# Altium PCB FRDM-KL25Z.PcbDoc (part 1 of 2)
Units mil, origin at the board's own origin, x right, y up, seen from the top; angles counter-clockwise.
Board outline 3200 x 2100 mil, 2 copper layers (Top Layer, Bottom Layer), stack 42.17 mil thick; 0 components, 164 nets, 466 pads, 402 vias.
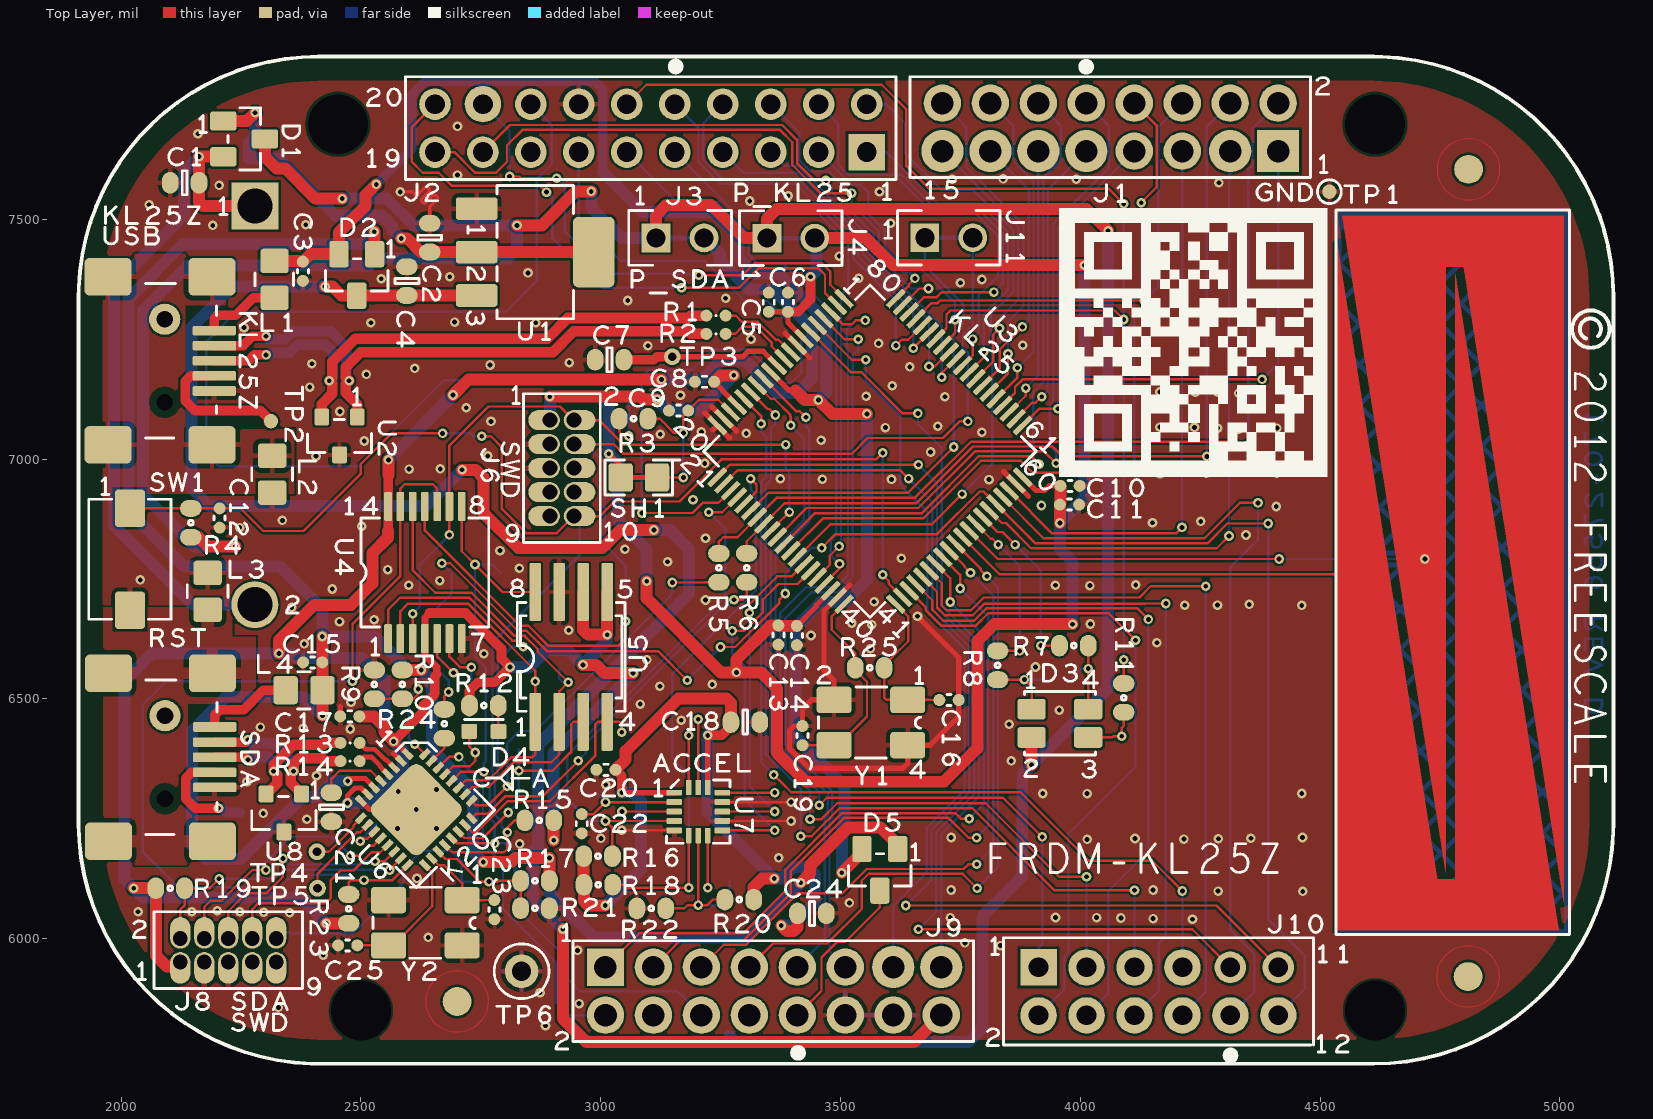
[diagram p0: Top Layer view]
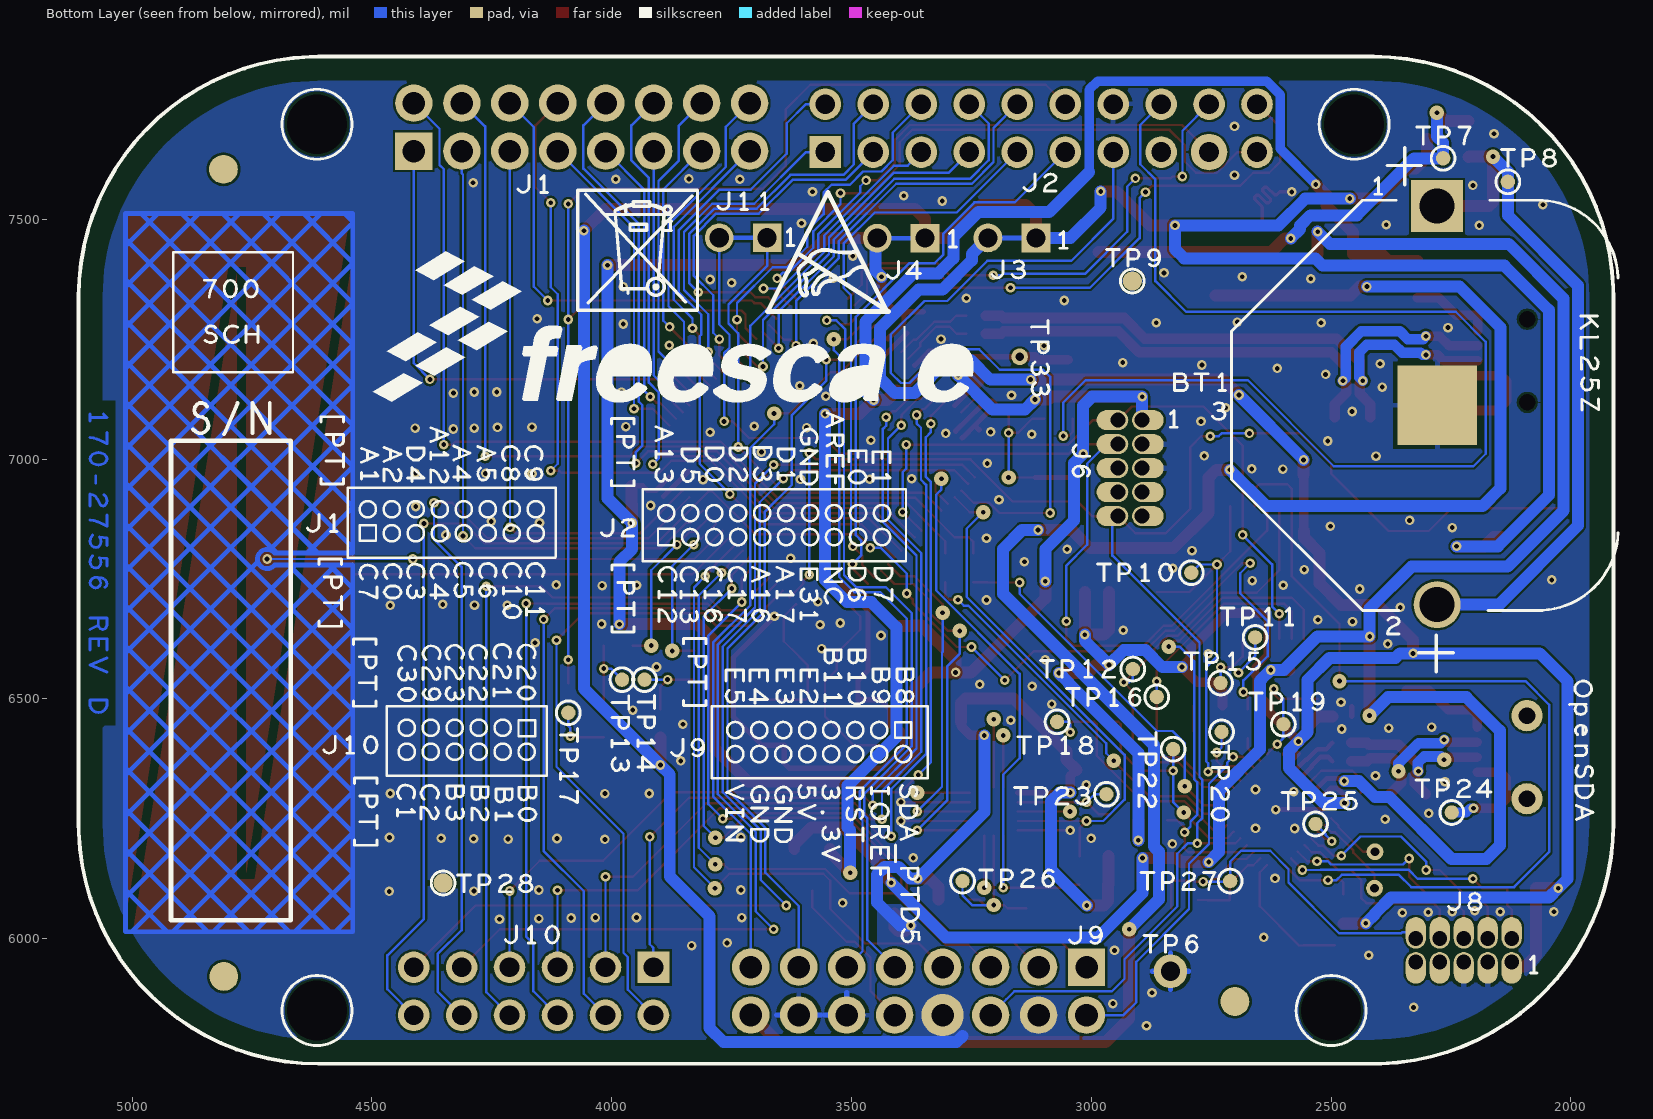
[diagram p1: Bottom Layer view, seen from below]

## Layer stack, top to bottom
Top Solder: solder mask 0.4, Solder Resist, Dk 3.5
Top Layer: signal copper 1.4
Dielectric1: core 39.3701, FR-4, Dk 4.8
Bottom Layer: signal copper 1.4
Bottom Solder: solder mask 0.4, Solder Resist, Dk 3.5

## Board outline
2007.77,5944.71 1988.16,5973.66 1970.61,6003.91 1955.22,6035.31 1942.06,6067.71 1931.18,6100.94 1922.66,6134.86 1916.51,6169.28 1912.79,6204.05 1911.5,6239 1911.5,7339 1911.84,7357.45 1914.34,7392.26 1919.27,7426.81 1926.59,7460.93 1936.28,7494.46 1948.28,7527.23 1962.54,7559.08 1978.99,7589.87 1997.54,7619.43 2018.11,7647.62 2040.6,7674.31 2064.89,7699.36 2090.87,7722.67 2118.42,7744.1 2147.39,7763.55 2177.65,7780.94 2209.05,7796.18 2241.43,7809.19 2274.64,7819.91 2308.52,7828.28 2342.9,7834.27 2377.62,7837.85 2412.5,7839 4611.5,7839 4628.85,7838.7 4663.67,7836.27 4698.23,7831.41 4732.37,7824.16 4765.93,7814.54 4798.73,7802.61 4830.61,7788.41 4861.43,7772.03 4891.03,7753.54 4919.27,7733.03 4946.01,7710.59 4971.12,7686.35 4994.48,7660.41 5015.97,7632.91 5035.49,7603.98 5052.94,7573.75 5068.25,7542.38 5081.33,7510.02 5092.12,7476.83 5100.56,7442.97 5106.63,7408.59 5110.28,7373.88 5111.5,7339 5111.5,6239 5111.2,6221.65 5108.77,6186.83 5103.91,6152.27 5096.66,6118.13 5087.04,6084.57 5075.11,6051.77 5060.91,6019.89 5044.53,5989.07 5026.04,5959.47 5005.53,5931.23 4983.09,5904.49 4958.85,5879.38 4932.91,5856.02 4905.41,5834.53 4876.48,5815.01 4846.25,5797.56 4814.88,5782.25 4782.52,5769.17 4749.33,5758.38 4715.47,5749.94 4681.09,5743.87 4646.38,5740.22 4611.5,5739 2412.5,5739 2396.01,5739.27 2361.13,5741.64 2326.49,5746.44 2292.27,5753.64 2258.63,5763.21 2225.75,5775.11 2193.77,5789.27 2162.87,5805.62 2133.17,5824.09 2104.84,5844.59 2078.01,5867.02 2052.81,5891.26 2029.35,5917.2

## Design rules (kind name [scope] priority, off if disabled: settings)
AssemblyTestPointUsage [All] p1 off:
AssemblyTestpoint [All] p1 off: testpointundercomponent=TRUE minsize=40 maxsize=100 preferedsize=60 minholesize=0 maxholesize=40 preferedholesize=32 testpointgrid=1 usegrid=TRUE gridtolerance=0.01 allowsidetop=TRUE allowsidebottom=TRUE
Clearance Clearance_1 [(ObjectKind = 'Region') And ((Net = '$Net77') Or (Net = '$Net152')) vs InPoly] p1: gap=10
Clearance Clearance_SpecialPoly [IsKeepout vs (ObjectKind = 'Poly') And (Layer = 'Bottom Layer') And (Net = 'p3v3')] p2: gap=50
Clearance Clearance_Keepout-Poly [IsKeepout vs InPoly And Not((Layer = 'Bottom Layer') And (Net = 'p3v3'))] p3: gap=50
Clearance [All] p4: gap=5
FabricationTestPointUsage [All] p1 off: valid=0 allowmultiple=FALSE
FabricationTestpoint [All] p1 off: side=3 testpointundercomponent=TRUE minsize=40 maxsize=100 preferedsize=60 minholesize=0 maxholesize=40 preferedholesize=32 testpointgrid=1 allowsidetop=TRUE allowsidebottom=TRUE usegrid=TRUE gridtolerance=0.01
HoleSize HoleSize_LargerThenPAD [(ObjectKind = 'Pad') And (PadIsPlated = 'True') And (HoleDiameter >= (PadXSize_TopLayer Or PadYSize_TopLayer))] p1: absolutevalues=TRUE maxlimit=2 minlimit=1 maxpercent=80.000 minpercent=20.000
HoleSize [All] p2: absolutevalues=TRUE maxlimit=125 minlimit=1 maxpercent=80.000 minpercent=20.000
MinimumAnnularRing [IsVia Or ((ObjectKind = 'Pad') And (PadIsPlated = 'True'))] p1: minimumring=0
PasteMaskExpansion [All] p1 off: expansion=0
PolygonConnect PolygonConnect_1 [(ObjectKind = 'Poly') And (Name = 'B-p3v3')] p1: connectstyle=Direct reliefconductorwidth=10 reliefentries=4 polygonreliefangle="90 Angle" airgapwidth=10
PolygonConnect PolygonConnect_Via [IsVia] p2: connectstyle=Direct reliefconductorwidth=10 reliefentries=4 polygonreliefangle="90 Angle" airgapwidth=10
PolygonConnect CAM_PolygonConnect_$Net40 [InNet('$Net40')] p3: connectstyle=Relief reliefconductorwidth=10 reliefentries=4 polygonreliefangle="90 Angle" airgapwidth=10
PolygonConnect CAM_PolygonConnect_$Net137 [InNet('$Net137')] p4: connectstyle=Relief reliefconductorwidth=10 reliefentries=4 polygonreliefangle="90 Angle" airgapwidth=10
PolygonConnect CAM_PolygonConnect_$Net136 [InNet('$Net136')] p5: connectstyle=Relief reliefconductorwidth=25 reliefentries=4 polygonreliefangle="90 Angle" airgapwidth=10
PolygonConnect CAM_PolygonConnect_GND [InNet('GND')] p6: connectstyle=Relief reliefconductorwidth=10 reliefentries=4 polygonreliefangle="90 Angle" airgapwidth=8
PolygonConnect [All] p7: connectstyle=Relief reliefconductorwidth=10 reliefentries=4 polygonreliefangle="90 Angle" airgapwidth=10
RoutingVias [All] p1: holewidth=28 width=50 viastyle="Through Hole" minholewidth=10 minwidth=20 maxholewidth=28 maxwidth=50
SilkToSilkClearance [All] p1 off: silktosilkclearance=10
SilkToSolderMaskClearance [IsPad] p1 off: minsilkscreentomaskgap=10 clearancetoexposedcopper=TRUE
SolderMaskExpansion [All] p1 off: expansion=4
Width [All] p1: maxlimit=30 minlimit=5 preferedwidth=10 minimp=50.000000 maximp=50.000000 favimp=50.000000
22 further rules are at their usual default settings.

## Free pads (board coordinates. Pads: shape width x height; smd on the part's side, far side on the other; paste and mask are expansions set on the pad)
  rrect25% 63x79 smd paste+0 mask+2: 1(2018.5,6684.7) 1(2018.5,6897.3)
  oval 35x45 smd paste+0 mask+2: 1(2072.4,6105.2) 1(2102.5,7576) 1(2132.4,6105.2) 1(2162.5,7576) 1(2726.5,6486) 1(2786.5,6486) 1(2833,6063.5) 1(2833,6120.5) 1(2842,6246.5) 1(2893,6063.5) 1(2893,6120.5) 1(2902,6246.5) 1(2964.5,6172) 1(2965,6112.5) 1(2988.5,7207) 1(3024.5,6172) 1(3025,6112.5) 1(3038.5,7084) 1(3048.5,7207) 1(3075.5,6063) 1(3098.5,7084) 1(3135.5,6063) 1(3259,6081.5) 1(3271.5,6451.5) 1(3319,6081.5) 1(3331.5,6451.5) 1(3410.5,6052.5) 1(3470.5,6052.5) 1(3531,6564.8) 1(3591,6564.8) 1(3956.5,6611) 1(4016.5,6611)
  round 10 / inner rect 10x10 / far side round 10 hole 35 unplated mask+14.5: 1(2091.05,7118.19)
  round 10 smd paste-5 mask+29: 1(2091.05,7291.41) 1(2091.85,6464.81)
  round 65.11 / inner rect 10x10 / far side round 10 hole 35 mask-13.05: 1(2091.05,7291.41)
  round 10 / inner rect 10x10 / far side round 65.05 hole 35 unplated mask+14.5: 1(2091.85,6291.59)
  round 65.11 / inner rect 10x10 / far side round 65.13 hole 35 mask-13.05: 1(2091.85,6464.81)
  round 10 smd far side paste-5 mask+29: 1(2091.85,6464.81)
  oval 42x66 hole 31 copper offset 0,-12 paste-33 mask+2: 1(2123.5,5951) 3(2173.5,5951) 5(2223.5,5951) 7(2273.5,5951) 9(2323.5,5951)
  round 30 smd far side paste-15 mask+2: 1(2131.5,7578) 1(2248.5,6263) 1(2266.5,7627) 1(2532.5,6239) 1(2599.5,6447) 1(2658.5,6628) 1(2710.5,6120) 1(2728.5,6431) 1(2730.5,6533) 1(2791.5,6763) 1(2829.5,6395) 1(2863.5,6504) 1(2913.5,6562) 1(2968.5,6301) 1(3071.5,6452) 1(3268.5,6120) 1(3931.5,6540) 1(3978.5,6540) 1(4090.5,6471)
  oval 45x35 smd paste+0 mask+2: 1(2145.5,6837) 1(2145.5,6897) 1(2438.5,6244) 1(2438.5,6304) 1(2474.5,6032) 1(2474.5,6092) 1(2528,6500) 1(2528,6560) 1(2586.5,6500) 1(2586.5,6560) 1(2596,7341) 1(2596,7401) 1(2643.5,7431.5) 1(2643.5,7491.5) 1(2674.1,6417.9) 1(2674.1,6477.9) 1(3246.5,6743) 1(3246.5,6803) 1(3304.5,6743) 1(3304.5,6803) 1(3827.5,6540) 1(3827.5,6600) 1(4090.5,6472) 1(4090.5,6532)
  rrect25% 59x51 smd paste+0 mask+2: 1(2180.5,6685.5) 1(2315,6930) 1(2320,7336) 1(2320,7413)
  rrect25% 59x51 smd paste-29.5 mask+4.5: 1(2180.5,6762.5) 1(2315,7007)
  rrect25% 90x20 smd paste+0 mask+2: 1(2194.4,7267.79) 1(2195.2,6441.19) 2(2194.4,7236.3) 2(2195.2,6409.7) 3(2194.4,7204.8) 3(2195.2,6378.2) 4(2194.4,7173.3) 4(2195.2,6346.7) 5(2194.4,7141.81) 5(2195.2,6315.21)
  round 25 smd paste+0 mask+2: 1(2205.5,6857) 1(2205.5,6897) 1(2379,7371.5) 1(2379,7411.5) 1(2379.5,6576) 1(2419.5,6576) 1(2452.5,5986) 1(2457,6463.5) 1(2457.5,6370) 1(2457.5,6408) 1(2492.5,5986) 1(2497,6463.5) 1(2497.5,6370) 1(2497.5,6408) 1(2778.5,6040.5) 1(2778.5,6080.5) 1(2960.5,6219.5) 1(2960.5,6259.5) 1(2991,6352) 1(3031,6352) 1(3142.5,7101) 1(3182.5,7101) 1(3196.5,7161) 1(3220.5,7261) 1(3220.5,7299) 1(3236.5,7161) 1(3260.5,7261) 1(3260.5,7299) 1(3350.5,7307) 1(3350.5,7347) 1(3370.5,6613) 1(3370.5,6653) 1(3390.5,7307) 1(3390.5,7347) 1(3409,6612) 1(3409,6652) 1(3420.7,6403.3) 1(3420.7,6443.3) 1(3706.3,6497.5) 1(3746.3,6497.5) 1(3957.5,6905) 1(3958.5,6944) 1(3997.5,6905) 1(3998.5,6944)
  rrect25% 55x40 smd paste+0 mask+2: 1(2213.2,7630.1) 1(2213.2,7704.9) 1(2299.8,7667.5)
  round 98 / inner rect 10x10 / far side round 98 hole 73 mask+2: 1(2279,6696.4)
  rect 155.91x155.91 smd far side paste-77.95 mask-43.95: 1(2279,7111.95)
  rect 165.94x165.94 smd far side paste-82.97 mask-3.05: 1(2279,7111.95)
  rect 98x98 / inner rect 10x10 / far side rect 108.04x108.04 hole 73 mask+2: 1(2279,7527.5)
  rect 98x98 smd far side paste-49 mask-15: 1(2279,7527.5)
  rrect25% 31x35 smd paste+0 mask+2: 1(2302.5,6301.5) 1(2339.5,6222.5) 1(2376.5,6301.5) 1(2418.5,7087.5) 1(2492.5,7087.5)
  round 30 smd paste-15 mask+2: 1(2312.5,7079)
  rrect25% 51x59 smd paste+0 mask+2: 1(2343,6518) 1(2420,6518) 1(3041.5,6961.5) 1(3117.5,6961.5)
  round 35 / inner rect 10x10 / far side round 35 hole 18 mask+2: 1(2408.5,6181) 1(2409.5,6105) 1(3149.5,7213)
  round 10 / inner rect 10x10 / far side round 10 hole 125 unplated mask+59.5: 1(2452,7698) 1(2500,5850) 1(4614.5,5850) 1(4614.5,7698)
  rrect25% 40x55 smd paste+0 mask+2: 1(2454.1,7427.3) 1(2491.5,7340.7) 1(2528.9,7427.3) 1(3544.6,6186.8) 1(3582,6100.2) 1(3619.4,6186.8)
  rrect25% 31x35 smd paste-17.5 mask+18.5: 1(2455.5,7008.5)
  rrect25% 16x60 smd paste+0 mask+2: 1(2556.7,6625.5) 2(2582.29,6625.5) 3(2607.88,6625.5) 4(2633.47,6625.5) 5(2659.06,6625.5) 6(2684.65,6625.5) 7(2710.24,6625.5) 8(2710.24,6901.1) 9(2684.65,6901.1) 10(2659.06,6901.1) 11(2633.47,6901.1) 12(2607.88,6901.1) 13(2582.29,6901.1) 14(2556.7,6901.1)
  rrect25% 25.28x12 smd rot 135 paste+0 mask+2.41: 1(2597.43,6384.58) 2(2583.5,6370.65) 3(2569.57,6356.72) 4(2555.64,6342.79) 5(2541.71,6328.86) 6(2527.78,6314.93) 7(2513.85,6301) 8(2499.92,6287.07)
  rrect25% 145x145 smd rot 45 paste-100.41: 1(2615.5,6269)
  round 60 smd paste-30 mask+30: 1(2700.7,5868.9) 1(4808.5,5921) 1(4809.5,7604)
  round 60 smd far side paste-30 mask+30: 1(2700.7,5868.9) 1(4808.7,5921.1) 1(4809.5,7604.1)
  rrect25% 73x55 smd paste+0 mask+2: 1(2711.27,6080.24) 1(3640.17,6497.84) 2(2557.73,6080.24) 2(3486.63,6497.84) 3(2557.73,5985.76) 3(3486.63,6403.36) 4(3640.17,6403.36)
  rrect25% 33x31 smd paste+0 mask+2: 1(2725.99,6432) 1(2787.01,6432)
  rrect25% 87x47 smd paste+0 mask+2: 1(2741.45,7340.95) 1(2741.45,7431.5)
  rrect25% 87x47 smd paste-43.5 mask-9.5: 1(2741.45,7522.05)
  round 76.04 / inner rect 10x10 / far side round 66 hole 41 mask-3.02: 1(2754.5,7740) 2(3913,5840) 3(4013,5940) 4(4013,5840) 5(4113,5940) 6(4113,5840) 7(4213,5940) 8(4213,5840) 10(4313,5840) 12(4413,5840)
  round 60 smd paste-30 mask+4: 1(2835.1,5932)
  round 70.04 / inner rect 10x10 / far side round 70.04 hole 40 mask-3.02: 1(2835.1,5932)
  round 60 smd far side paste-30 mask+4: 1(2835.1,5932)
  rrect25% 24x121 smd paste+0 mask+2: 1(2863.5,6452.13) 2(2913.5,6452.13) 3(2963.5,6452.13) 4(3013.5,6452.13) 5(3013.5,6722.79) 6(2963.5,6722.79) 8(2863.5,6722.79)
  oval 66x42 hole 31 copper offset -12,0 paste-33 mask+2: 1(2894,7081) 3(2894,7031) 5(2894,6981) 7(2894,6931) 9(2894,6881)
  round 30 smd far side paste-15 mask+19: 1(2914.5,7371)
  round 40.04 smd far side paste-20.02 mask-3.02: 1(2914.5,7371)
  rrect25% 87x147 smd paste+0 mask+2: 1(2985.55,7431.5)
  rect 78.02x78.01 / inner rect 10x10 / far side rect 78.02x78.01 hole 47 mask+2.01: 1(3010,5940.5)
  round 20 smd far side paste-10 mask+2: 1(3044.5,6265) 1(3183.81,6423.74) 1(3203.5,6457.4) 1(3223.19,6106.26) 1(3363.11,6304.37)
  rect 60x60 / inner rect 10x10 / far side rect 60x60 hole 40 mask+2: 1(3115.5,7461) 1(3346.5,7460.5) 1(3675.9,7461.4)
  rrect25% 32x12 smd paste-0.5 mask+2: 1(3153.3,6304.37) 2(3153.3,6284.69) 3(3153.3,6265) 4(3153.3,6245.31) 5(3153.3,6225.63) 9(3253.7,6225.63) 10(3253.7,6245.31) 11(3253.7,6265) 12(3253.7,6284.69) 13(3253.7,6304.37)
  rrect25% 11x48.79 smd rot 45 paste+0 mask+2.82: 1(3507.55,7334.42) 2(3493.62,7320.5) 3(3479.71,7306.59) 4(3465.79,7292.66) 5(3451.87,7278.75) 6(3437.95,7264.82) 7(3424.03,7250.91) 8(3410.11,7236.99) 9(3396.19,7223.07) 10(3382.27,7209.15) 11(3368.35,7195.23) 12(3354.43,7181.31) 13(3340.51,7167.39) 14(3326.59,7153.47) 15(3312.68,7139.55) 16(3298.75,7125.63) 17(3284.84,7111.71) 18(3270.91,7097.79) 19(3257,7083.88) 20(3243.08,7069.95) 41(3615.45,6697.58) 42(3629.38,6711.5) 43(3643.29,6725.41) 44(3657.21,6739.34) 45(3671.13,6753.25) 46(3685.05,6767.18) 47(3698.97,6781.09) 48(3712.89,6795.01) 49(3726.81,6808.93) 50(3740.73,6822.85) 51(3754.65,6836.77) 52(3768.57,6850.69) 53(3782.49,6864.61) 54(3796.41,6878.53) 55(3810.32,6892.45) 56(3824.25,6906.37) 57(3838.16,6920.29) 58(3852.09,6934.21) 59(3866,6948.12) 60(3879.92,6962.05)
  rect 76.04x76.04 / inner rect 10x10 / far side rect 66x66 hole 41 mask-3.02: 1(3554.5,7640) 1(3913,5940)
  rrect25% 59x43 smd paste+0 mask+2: 1(3898.44,6478.53) 2(3898.44,6419.47) 3(4016.56,6419.47) 4(4016.56,6478.53)
  round 30 smd far side paste-15: 1(4351.5,6116)
  round 40.04 smd far side paste-20.02: 1(4351.5,6116)
  rect 88.04x88.04 / inner rect 10x10 / far side rect 78x78 hole 47 mask-3.02: 1(4412.5,7642)
  round 30 smd paste-15 mask+19: 1(4519.4,7557.4)
  rect 107.99x107.99 on Mech2: 1(11422,6085.5)
  rect 157.99x108 on Mech2: 1(11422,6366.5)
  rect 108x158 on Mech2: 1(11422,7209.5)
  rect 57.99x57.99 on Mech2: 1(11422,7771.5)
  oval 42x66 hole 31 copper offset 0,12 paste-33 mask+2: 2(2123.5,6000) 4(2173.5,6000) 6(2223.5,6000) 8(2273.5,6000) 10(2323.5,6000)
  oval 66x42 hole 31 copper offset 12,0 paste-33 mask+2: 2(2944,7081) 4(2944,7031) 6(2944,6981) 8(2944,6931) 10(2944,6881)
  round 78 / inner rect 10x10 / far side round 78 hole 47 mask+2: 2(3010.04,5840.5) 2(4412.5,7742) 3(3110,5940.54) 4(3110.04,5840.54) 4(4312.5,7742) 5(3210,5940.58) 5(4212.5,7642) 6(3210.04,5840.58) 6(4212.5,7742) 7(3310,5940.62) 7(4112.5,7642) 8(4112.5,7742) 9(3410,5940.65) 10(4012.5,7742) 11(3510,5940.69) 12(3410.04,5840.65) 12(3912.5,7742) 14(3510.04,5840.69) 14(3812.5,7742) 16(3610.04,5840.73) 16(3712.5,7742) 18(3710.04,5840.77)
  round 60 / inner rect 10x10 / far side round 60 hole 40 mask+2: 2(3215.5,7461) 2(3446.5,7460.5) 2(3775.9,7461.4)
  round 66 / inner rect 10x10 / far side round 66 hole 41 mask+2: 2(3554.5,7740) 3(3454.5,7640) 4(3454.5,7740) 5(3354.5,7640) 6(3354.5,7740) 7(3254.5,7640) 8(3254.5,7740) 9(3154.5,7640) 9(4313,5940) 10(3154.5,7740) 11(3054.5,7640) 11(4413,5940) 12(3054.5,7740) 13(2954.5,7640) 14(2954.5,7740) 15(2854.5,7640) 16(2854.5,7740) 18(2654.5,7740) 19(2654.5,7640)
  round 88.04 / inner rect 10x10 / far side round 78 hole 47 mask-3.02: 3(4312.5,7642) 9(4012.5,7642) 11(3912.5,7642) 13(3610,5940.73) 13(3812.5,7642) 15(3710,5940.77) 15(3712.5,7642)
  rrect25% 73x55 smd paste-36.5 mask-2.5: 4(2711.27,5985.76)
  rrect25% 12x32 smd paste-0.5 mask+2: 6(3183.81,6214.8) 7(3203.5,6214.8) 8(3223.19,6214.8) 14(3223.19,6315.2) 15(3203.5,6315.2) 16(3183.81,6315.2)
  rrect25% 24x121 smd paste-60.5 mask+4: 7(2913.5,6722.79)
  rrect25% 12x25.27 smd rot 135 paste+0 mask+2.41: 9(2499.92,6250.93) 10(2513.85,6237) 11(2527.78,6223.07) 12(2541.71,6209.14) 13(2555.64,6195.21) 14(2569.57,6181.28) 15(2583.5,6167.35) 16(2597.43,6153.42)
  round 78 / inner rect 10x10 / far side round 88.04 hole 47 mask+2: 10(3310.04,5840.62)
  rrect25% 12x25.27 smd rot 45 paste+0 mask+2.41: 17(2633.57,6153.42) 18(2647.5,6167.35) 19(2661.43,6181.28) 20(2675.36,6195.21) 21(2689.29,6209.14) 22(2703.22,6223.07) 23(2717.15,6237) 24(2731.08,6250.93)
  round 66 / inner rect 10x10 / far side round 76.04 hole 41 mask+2: 17(2754.5,7640)
  rrect25% 11x48.79 smd rot 135 paste+0 mask+2.82: 21(3243.08,6962.05) 22(3257,6948.12) 23(3270.91,6934.21) 24(3284.84,6920.29) 25(3298.75,6906.37) 26(3312.68,6892.45) 27(3326.59,6878.53) 28(3340.51,6864.61) 29(3354.43,6850.69) 30(3368.35,6836.77) 31(3382.27,6822.85) 32(3396.19,6808.93) 33(3410.11,6795.01) 34(3424.03,6781.09) 35(3437.95,6767.18) 36(3451.87,6753.25) 37(3465.79,6739.34) 38(3479.71,6725.41) 39(3493.62,6711.5) 40(3507.55,6697.58) 61(3879.92,7069.95) 62(3866,7083.88) 63(3852.09,7097.79) 64(3838.16,7111.71) 65(3824.25,7125.63) 66(3810.32,7139.55) 67(3796.41,7153.47) 68(3782.49,7167.39) 69(3768.57,7181.31) 70(3754.65,7195.23) 71(3740.73,7209.15) 72(3726.81,7223.07) 73(3712.89,7236.99) 74(3698.97,7250.91) 75(3685.05,7264.82) 76(3671.13,7278.75) 77(3657.21,7292.66) 78(3643.29,7306.59) 79(3629.38,7320.5) 80(3615.45,7334.42)
  rrect25% 25.28x12 smd rot 45 paste+0 mask+2.41: 25(2731.08,6287.07) 26(2717.15,6301) 27(2703.22,6314.93) 28(2689.29,6328.86) 29(2675.36,6342.79) 30(2661.43,6356.72) 31(2647.5,6370.65) 32(2633.57,6384.58)
  rrect25% 98x78 smd paste+0 mask+2: B01(1972.94,7029.6) B01(1972.94,7380) B01(1973.74,6203) B01(1973.74,6553.4) B01(2189.48,7029.6) B01(2189.48,7380)
  rrect25% 98x78 smd paste-49 mask-15: B01(2190.28,6203) B01(2190.28,6553.4)

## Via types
v1: diameter 20/20 (per signal layer), hole 10, Top Layer to Bottom Layer, 372 vias
v2: diameter 20/30 (per signal layer), hole 10, Top Layer to Bottom Layer, 25 vias
v3: diameter 20/30.04 (per signal layer), hole 10, Top Layer to Bottom Layer, 5 vias

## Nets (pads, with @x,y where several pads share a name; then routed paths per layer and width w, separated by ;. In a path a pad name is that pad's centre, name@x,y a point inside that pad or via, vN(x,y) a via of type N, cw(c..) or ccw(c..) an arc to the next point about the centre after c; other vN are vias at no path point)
$Net0: pad.1@3675.9,7461.4 pad.2@3775.9,7461.4 pad.4@2944,7031 pad.11@2633.47,6901.1 pad.26@3312.68,6892.45 | length 3349.5
  Top Layer w5: 2633.47,6858.53 pad.11@2633.47,6901.1 ; 2633.5,6858.5 2633.5,6850.7 2831.95,6652.25 2849.55,6652.25 2891.4,6610.4 3036.1,6610.4 3052,6626.3 v1(3052,6661.7) ; pad.4@2944,7031 3027.3,7031 3047.5,7010.8 3523.4,7010.8 3556.4,7043.8 3713.6,7043.8 3748.2,7078.4 v1(3765.7,7078.4) ; pad.26@3312.68,6892.45 3349.83,6929.6 3640.5,6929.6 v1(3736,7025.1)
  Bottom Layer w5: pad.4@2944,7031 2968,7031 3008.5,6990.5 3008.5,6821.5 3052,6778 v1(3052,6661.7) ; pad.1@3675.9,7461.4 3675.9,7402.5 3756.4,7322 3756.4,7282.3 3736,7261.9 v1(3736,7025.1) ; v1(3765.7,7078.4) 3765.7,7220.8 3754.4,7232.1 3754.4,7259.1 3775.9,7280.6 pad.2@3775.9,7461.4
  Bottom Layer w10: pad.1@3675.9,7461.4 pad.2@3775.9,7461.4
$Net3: pad.1@2491.5,7340.7 pad.1@2596,7341 pad.1@2741.45,7340.95 pad.18@3710.04,5840.77 | length 4171.8
  Top Layer w25: v1(2425.5,7359.5) 2441.2,7359.5 2460,7340.7 pad.1@2491.5,7340.7 2529,7340.7 2529.3,7341 pad.1@2596,7341 2636,7341 2636.05,7340.95 pad.1@2741.45,7340.95 ; v1(2711,6977.5) 2739.5,6977.5 2755.5,6961.5 2755.5,6887.5 2829,6814 3003,6814 3041,6852 v1(3111,6852) ; v2(2921,6019.7) 2921,5833.5 2970.5,5784 3653.33,5784 pad.18@3710.04,5840.77
  Bottom Layer w25: v1(2425.5,7359.5) 2232.2,7359.5 2147.2,7274.5 2147.2,6938.7 2183.9,6902 2635.5,6902 v1(2711,6977.5) ; v2(2921,6019.7) 2859.2,6081.5 2859.2,6181.7 2869.25,6191.75 2869.25,6403.75 3184,6718.5 3184,6812.5 3144.5,6852 v1(3111,6852)
$Net4: pad.1@2528,6500 pad.1@2586.5,6500 pad.1@2599.5,6447 pad.32@2633.57,6384.58 | length 265.1
  Top Layer w5: pad.1@2528,6500 pad.1@2586.5,6500 2609.7,6500 2619.7,6510 v1(2619.7,6520.5) ; v1(2612.5,6405.12) 2613.03,6405.12 pad.32@2633.57,6384.58
  Bottom Layer w5: v1(2612.5,6405.12) 2599.5,6418.12 pad.1@2599.5,6447 2599.5,6500.3 v1(2619.7,6520.5)
$Net5: pad.2@3010.04,5840.5 pad.30@2661.43,6356.72 | length 762.6
  Top Layer w5: pad.30@2661.43,6356.72 2683.71,6379 v1(2704.5,6379)
  Bottom Layer w5: v1(2704.5,6379) 2716.88,6366.62 2716.88,6360.82 2754.7,6323 2754.7,6197.6 2796.25,6156.05 2796.25,6061.45 2906.3,5951.4 2906.3,5867.1 2932.92,5840.48 2963.54,5840.48 pad.2@3010.04,5840.5
$Net6: pad.1@2248.5,6263 pad.4@2195.2,6346.7 | length 234.1
  Top Layer w20: pad.4@2195.2,6346.7 2146.9,6346.7 2134.5,6334.3 2134.5,6292 2154.5,6272 v1(2203.2,6272)
  Bottom Layer w20: v1(2203.2,6272) 2209.5,6272 2218.5,6263 pad.1@2248.5,6263
$Net7: pad.1@2658.5,6628 pad.5@2659.06,6625.5 | length 173.4
  Top Layer w5: pad.5@2659.06,6625.5 2659.06,6588 2669.66,6577.4 2670.3,6577.4 v1(2693.2,6554.5)
  Bottom Layer w5: pad.1@2658.5,6628 2658.5,6589.2 v1(2693.2,6554.5)
$Net8: pad.1@2730.5,6533 pad.6@2684.65,6625.5 | length 125.5
  Top Layer w5: pad.6@2684.65,6625.5 2684.65,6588 2706.65,6566 v1(2730.5,6566)
  Bottom Layer w5: pad.1@2730.5,6533 v1(2730.5,6566)
$Net9: pad.5@4212.5,7642 pad.58 | length 1186.8
  Top Layer w5: pad.58@3852.09,6934.21 3941.3,6845 4199.5,6845 v1(4212,6857.5)
  Bottom Layer w5: v1(4212,6857.5) 4212,7360.71 4212.5,7360.98 pad.5@4212.5,7642
$Net10: pad.13@3812.5,7642 pad.67 | length 561.2
  Top Layer w5: pad.67@3796.41,7153.47 3831.7,7188.76 3831.7,7227.9 v1(3879.3,7275.5)
  Bottom Layer w5: pad.13@3812.5,7642 3892.2,7562.3 3892.2,7288.4 v1(3879.3,7275.5)
$Net11: pad.7@3310,5940.62 pad.50 | length 1374.5
  Top Layer w5: pad.7@3310,5940.62 3359.28,5989.9 3472.1,5989.9 3544.3,6062.1 3544.3,6120.61 3558.89,6135.2 3754.6,6135.2 v2(3784.8,6105) ; pad.50@3740.73,6822.85 3792.8,6770.78 3792.8,6767.84 v1(3805.18,6755.46)
  Bottom Layer w5: v2(3784.8,6105) 3828.5,6148.7 3828.5,6732.14 v1(3805.18,6755.46)
$Net12: pad.5@3210,5940.58 pad.49 | length 1369.1
  Top Layer w5: pad.5@3210,5940.58 3256.54,5987.12 3303.12,5987.12 3410.2,6094.2 3503.74,6094.2 3554.74,6145.2 3756.8,6145.2 3766.6,6155 v2(3784.1,6155) ; pad.49@3726.81,6808.93 3758,6777.74 3758,6776 v1(3771,6763)
  Bottom Layer w5: v1(3771,6763) 3818.5,6715.5 3818.5,6189.4 v2(3784.1,6155)
$Net13: pad.3@3110,5940.54 pad.48 | length 1481.1
  Top Layer w5: pad.3@3110,5940.54 3142.88,5973.44 3166.54,5997.12 3298.82,5997.12 3396,6094.3 3396,6140.29 3507.51,6251.8 3725,6251.8 3766.3,6210.5 v2(3783.8,6210.5) ; pad.48@3712.89,6795.01 3749.5,6758.4 v1(3749.5,6730)
  Bottom Layer w5: v1(3749.5,6730) 3808.5,6671 3808.5,6235.2 v2(3783.8,6210.5)
$Net14: pad.1@3010,5940.5 pad.47 | length 1507
  Top Layer w5: pad.1@3010,5940.5 3054.29,5984.83 3080.44,6011 3297,6011 3385,6099 3385,6143.44 3503.36,6261.8 3739.34,6261.8 3750.99,6250.15 v1(3768.49,6250.15) ; pad.47@3698.97,6781.09 3728.68,6751.38 v1(3728.68,6701.86)
  Bottom Layer w5: v1(3728.68,6701.86) 3798.5,6632.04 3798.5,6280.16 v1(3768.49,6250.15)
$Net15: pad.9@3253.7,6225.63 pad.35 | length 792.9
  Top Layer w5: pad.9@3253.7,6225.63 v1(3363.11,6225.63) ; v2(3274.5,6641.6) 3298.6,6641.6 3315,6658 3315.7,6658 3338,6680.3 3338,6706.5 3371,6739.5 3410.27,6739.5 pad.35@3437.95,6767.18
  Bottom Layer w5: v2(3274.5,6641.6) 3274.5,6593.4 3300.6,6567.3 3300.6,6288.14 v1(3363.11,6225.63)
$Net16: pad.11@3253.7,6265 pad.34 | length 712.2
  Top Layer w5: pad.11@3253.7,6265 v1(3363.11,6265) ; v2(3310.07,6679.6) 3310.07,6697.1 3368.25,6755.28 3398.22,6755.28 pad.34@3424.03,6781.09
  Bottom Layer w5: v2(3310.07,6679.6) 3310.07,6597.67 3311.4,6596.34 3311.4,6316.71 v1(3363.11,6265)
$Net17: pad.1@3025,6112.5 pad.6@3183.81,6214.8 pad.25@3298.75,6906.37 | length 1281.9
  Top Layer w5: pad.1@3025,6112.5 3050,6112.5 3056.24,6106.26 v1(3183.81,6106.26) pad.6@3183.81,6214.8 ; pad.25@3298.75,6906.37 3324.88,6932.5 3324.88,6946.62 v2(3312.5,6959)
  Bottom Layer w5: v1(3183.81,6106.26) 3183.81,6341.69 3149.5,6376 3149.5,6552 3323.25,6725.75 3323.25,6925.75 3312.5,6936.5 v2(3312.5,6959)
$Net18: pad.1@3024.5,6172 pad.4@3153.3,6245.31 pad.24@3284.84,6920.29 | length 1142.8
  Top Layer w5: pad.1@3024.5,6172 3024.5,6217.44 3024.39,6217.55 3024.39,6230.96 v1(3010.04,6245.31) pad.4@3153.3,6245.31 ; v2(3225.5,6889) 3253.55,6889 pad.24@3284.84,6920.29
  Bottom Layer w5: v1(3010.04,6245.31) 2975,6245.31 2930.5,6289.81 2930.5,6383.21 3260.01,6712.72 3260.01,6854.49 v2(3225.5,6889)
$Net21: pad.1@3827.5,6600 pad.53 | length 351.1
  Top Layer w5: pad.53@3782.49,6864.61 3813.22,6833.88 3816.62,6833.88 v1(3829,6821.5) ; pad.1@3827.5,6600 3873.74,6600 v2(3873.9,6599.84)
  Bottom Layer w5: v1(3829,6821.5) 3873.9,6776.6 v2(3873.9,6599.84)
$Net22: pad.1@3956.5,6611 pad.54 | length 362.9
  Top Layer w5: pad.54@3796.41,6878.53 3827.12,6847.82 3837.68,6847.82 v1(3864,6821.5) ; v2(3917.5,6611) pad.1@3956.5,6611
  Bottom Layer w5: v1(3864,6821.5) 3917.5,6768 v2(3917.5,6611)
$Net23: pad.11@3054.5,7640 pad.37 | length 1187.5
  Top Layer w5: pad.37@3465.79,6739.34 3491.6,6765.15 3491.6,6765.6 3498,6772 v1(3498,6781.4)
  Bottom Layer w5: pad.11@3054.5,7640 3159.5,7535 3243.79,7535 3308.5,7470.29 3308.5,7426.5 3326.5,7408.5 3379,7408.5 3491,7296.5 3491,6841.07 3479.3,6829.37 3479.3,6800.1 v1(3498,6781.4)
$Net24: pad.9@3154.5,7640 pad.36 | length 1163.6
  Top Layer w5: pad.36@3451.87,6753.25 3477.68,6779.06 3477.68,6798.38 v1(3497.1,6817.8)
  Bottom Layer w5: pad.9@3154.5,7640 3280.5,7514 3451.5,7514 3516.5,7449 3516.5,7357 3501,7341.5 3501,6826.32 3497.1,6822.42 v1(3497.1,6817.8)
$Net31: pad.3@3454.5,7640 pad.70 | length 747.2
  Top Layer w5: pad.70@3754.65,7195.23 3775.4,7215.98 v1(3775.4,7250.1)
  Bottom Layer w5: pad.3@3454.5,7640 3512.5,7582 3623.1,7582 3693.5,7511.6 3782.3,7511.6 3828.7,7465.2 3828.7,7381.7 3788.4,7341.4 3788.4,7263.1 v1(3775.4,7250.1)
$Net32: pad.1@3554.5,7640 pad.69 | length 689.3
  Top Layer w5: pad.69@3768.57,7181.31 3798.6,7211.34 v1(3798.6,7223.3)
  Bottom Layer w5: pad.1@3554.5,7640 3595,7640 3702.7,7532.3 3790.3,7532.3 3849.32,7473.28 3849.32,7352.6 3798.6,7301.88 v1(3798.6,7223.3)
$Net33: pad.15@3712.5,7642 pad.68 | length 576.5
  Top Layer w5: pad.68@3782.49,7167.39 3818.5,7203.4 3818.5,7259.7 v1(3831.5,7272.7)
  Bottom Layer w5: pad.15@3712.5,7642 3870.5,7484 3870.5,7332 3831.5,7293 v1(3831.5,7272.7)
$Net34: pad.5@3354.5,7640 pad.71 | length 685.3
  Top Layer w5: v1(3711.16,7170.27) 3711.16,7179.58 pad.71@3740.73,7209.15
  Bottom Layer w5: pad.5@3354.5,7640 3383.14,7611.36 3411.71,7611.36 3557,7466.07 3557,7431.6 3711.16,7277.44 v1(3711.16,7170.27)
$Net35: pad.7@3254.5,7640 pad.72 | length 747
  Top Layer w5: v1(3684.5,7192.96) 3696.7,7192.96 pad.72@3726.81,7223.07
  Bottom Layer w5: pad.7@3254.5,7640 3298,7596.5 3412.42,7596.5 3547,7461.92 3547,7427.2 3684.5,7289.7 v1(3684.5,7192.96)
$Net36: pad.11@3912.5,7642 pad.63 | length 569.2
  Top Layer w5: pad.63@3852.09,7097.79 3886.31,7132.01 v1(3886.31,7147.89)
  Bottom Layer w5: v1(3886.31,7147.89) 3912.5,7174.08 pad.11@3912.5,7642
$Net37: pad.9@4012.5,7642 pad.62 | length 623.1
  Top Layer w5: pad.62@3866,7083.88 3899.74,7117.62 3907.12,7117.62 v1(3919.5,7130)
  Bottom Layer w5: v1(3919.5,7130) 3932.5,7143 3932.5,7562 pad.9@4012.5,7642
$Net38: pad.7@4112.5,7642 pad.61 | length 691
  Top Layer w5: pad.61@3879.92,7069.95 3914.97,7105 v1(3953.5,7105)
  Bottom Layer w5: v1(3953.5,7105) 3953.5,7483 pad.7@4112.5,7642
$Net39: pad.1@2532.5,6239 pad.11@2527.78,6223.07 | length 87.7
  Top Layer w5: v1(2498.5,6203) 2503.37,6207.87 2512.58,6207.87 pad.11@2527.78,6223.07
  Bottom Layer w5: v1(2498.5,6203) 2510.88,6215.38 2510.88,6217.38 pad.1@2532.5,6239
$Net41: pad.1@2913.5,6562 pad.2@2913.5,6452.13 pad.12@2607.88,6901.1 pad.26@2717.15,6301 | length 988.7
  Top Layer w5: pad.12@2607.88,6901.1 2607.88,6858.52 2607.9,6768.25 2655.15,6721 2730.8,6721 2820.5,6631.3 2841.3,6631.3 2868.8,6603.8 2868.8,6598 v1(2932.4,6534.4) 2913.5,6515.5 pad.2@2913.5,6452.13 2913.5,6384.13 2897.07,6367.7 2818.2,6367.7 2766.7,6316.2 2732.35,6316.2 pad.26@2717.15,6301
  Bottom Layer w5: pad.1@2913.5,6562 2913.5,6541.7 2920.8,6534.4 v1(2932.4,6534.4)
$Net42: pad.1@2829.5,6395 pad.3@2963.5,6452.13 pad.22@2703.22,6223.07 | length 482.9
  Top Layer w5: pad.22@2703.22,6223.07 2716.39,6209.9 2754.4,6209.9 v2(2807.5,6263) ; v1(2829.5,6350.1) 2899.6,6350.1 2938.4,6388.9 2938.4,6446.53 2944,6452.13 pad.3@2963.5,6452.13
  Bottom Layer w5: v2(2807.5,6263) 2829.5,6285 v1(2829.5,6350.1) pad.1@2829.5,6395
$Net43: pad.1@3038.5,7084 pad.16@2854.5,7740 | length 2480.7
  Top Layer w5: pad.1@3038.5,7084 3038.5,7057 3047.5,7048 v1(3058.5,7048)
  Bottom Layer w5: pad.16@2854.5,7740 2898,7696.5 2898,7614.5 2866.4,7582.9 2866.4,7370.9 2802.5,7307 2240.3,7307 2177.5,7244.2 2177.5,7010.9 2203.4,6985 2494.5,6985 2674,7164.5 3011.5,7164.5 3058.5,7117.5 v1(3058.5,7048)
$Net44: pad.1@3071.5,6452 pad.4@3013.5,6452.13 pad.23@2717.15,6237 | length 533.1
  Top Layer w5: pad.23@2717.15,6237 2732.35,6221.8 2741.3,6221.8 2805.9,6286.4 2893.7,6286.4 2989.1,6381.8 2989.1,6447.23 2994,6452.13 pad.4@3013.5,6452.13 3039.27,6452.13 3043.8,6447.6 v1(3043.8,6430.1)
  Bottom Layer w5: v1(3043.8,6430.1) 3043.8,6447.6 3048.2,6452 pad.1@3071.5,6452
$Net45: pad.1@2213.2,7704.9 pad.1@2266.5,7627 pad.1@2643.5,7431.5 pad.1@2741.45,7431.5 pad.1@2985.55,7431.5 | length 978.2
  Top Layer w25: pad.1@2213.2,7704.9 2262.4,7704.9 v2(2279.5,7722) ; v1(2584,7460) 2596.5,7460 2625,7431.5 pad.1@2643.5,7431.5 pad.1@2741.45,7431.5 pad.1@2985.55,7431.5
  Bottom Layer w25: v2(2279.5,7722) 2279.5,7672.5 2266.5,7659.5 pad.1@2266.5,7627 2327.5,7627 2446.5,7508 2543.5,7508 2564.55,7486.95 2564.55,7479.45 v1(2584,7460)
$Net46: pad.1@2791.5,6763 pad.8@2710.24,6901.1 pad.8@2863.5,6722.79 pad.28@2689.29,6328.86 | length 860.5
  Top Layer w5: pad.28@2689.29,6328.86 2708.43,6348 v1(2756.5,6348) ; pad.8@2710.24,6901.1 2710.24,6807.76 v1(2738,6780) 2795.21,6722.79 pad.8@2863.5,6722.79
  Bottom Layer w5: v1(2756.5,6348) 2756.5,6365.5 2760.5,6369.5 2760.5,6565.4 2738,6587.9 v1(2738,6780) 2774.5,6780 pad.1@2791.5,6763
$Net47: pad.1@2419.5,6576 pad.1@2420,6518 pad.1@2528.9,7427.3 pad.1@2586.5,6560 pad.1@2893,6120.5 pad.1@3619.4,6186.8 pad.6@2527.78,6314.93 | length 4680.8
  Top Layer w11: v1(2472.5,6328.5) 2477.7,6333.7 2509.01,6333.7 pad.6@2527.78,6314.93
  Top Layer w25: v1(2419.5,6630) pad.1@2419.5,6576 2420,6575.5 pad.1@2420,6518 v2(2420,6465) ; v1(2528,7474) 2528,7428.2 pad.1@2528.9,7427.3 ; pad.1@2586.5,6560 v1(2626.1,6560) ; v1(2755.2,6159.5) 2813.5,6159.5 2822,6168 v1(2893,6168) pad.1@2893,6120.5 ; v1(3417,6116.5) 3436.45,6135.95 3436.45,6152.45 3515.8,6231.8 3583.8,6231.8 3619.4,6196.2 pad.1@3619.4,6186.8
  Bottom Layer w25: v2(2420,6465) 2381.5,6503.5 2218,6503.5 2148.2,6433.7 2148.2,6194.2 2176.4,6166 2249,6166 2378,6295 2408.4,6295 2441.9,6328.5 v1(2472.5,6328.5) ; v1(2528,7474) 2502.5,7448.5 2129.7,7448.5 2015.5,7334.3 2015.5,6892.5 2132,6776 2332,6776 2419.5,6688.5 v1(2419.5,6630) 2528.6,6630 2598.6,6560 v1(2626.1,6560) 2645.55,6540.55 2645.55,6540.35 2648.6,6537.3 2648.6,6393.9 2733.7,6308.8 2733.7,6181 v1(2755.2,6159.5) ; v1(2893,6168) 2893,6095.4 2986.4,6002 3302.5,6002 v1(3417,6116.5)
$Net49: pad.1@2474.5,6092 pad.10@2659.06,6901.1 pad.13@2582.29,6901.1 pad.16@2597.43,6153.42 | length 1998.8
  Top Layer w5: pad.1@2474.5,6092 2474.5,6117 2479.5,6122 v1(2506.5,6122) 2566.01,6122 pad.16@2597.43,6153.42 ; v2(2482.5,6537) 2482.5,6656 2582.3,6755.8 2582.3,6858.5 pad.13@2582.29,6901.1 2582.29,6938.6 2591.19,6947.5 2650.16,6947.5 2659.06,6938.6 pad.10@2659.06,6901.1
  Bottom Layer w5: v2(2482.5,6537) 2094.6,6537 2045.4,6487.8 2045.4,6180.6 2118.5,6107.5 2333,6107.5 2358.5,6133 2478,6133 2489,6122 v1(2506.5,6122)
$Net50: pad.8@4213,5840 pad.46 | length 1573.5
  Top Layer w5: pad.46@3685.05,6767.18 3711.18,6741.05 3711.18,6694.61 3721.43,6684.36 3771.62,6684.36 3798.56,6711.3 4123.38,6711.3 4146.68,6734.6 v1(4261.5,6734.6)
  Bottom Layer w5: pad.8@4213,5840 4261.5,5888.5 v1(4261.5,6734.6)
$Net51: pad.6@4113,5840 pad.45 | length 1455
  Top Layer w5: pad.45@3671.13,6753.25 3701.18,6723.2 3701.18,6690.46 3717.28,6674.36 3775.77,6674.36 3799.92,6698.51 4135.99,6698.51 4136.18,6698.7 v1(4178.4,6698.7)
  Bottom Layer w5: pad.6@4113,5840 4163.3,5890.3 4163.3,5989.5 4178.4,6004.6 v1(4178.4,6698.7)
$Net52: pad.4@4013,5840 pad.44 | length 1427.1
  Top Layer w5: pad.44@3657.21,6739.34 3691.18,6705.37 3691.18,6685.92 3714.2,6662.9 3778.46,6662.9 3804.07,6688.51 4119.09,6688.51 v1(4142.1,6665.5)
  Bottom Layer w5: pad.4@4013,5840 4058,5885 4058,6098.7 4142.1,6182.8 v1(4142.1,6665.5)
$Net53: pad.2@3913,5840 pad.43 | length 1406
  Top Layer w5: pad.43@3643.29,6725.41 3678,6690.7 3678,6684.1 3709.5,6652.6 3782.31,6652.6 3808.22,6678.51 4058.97,6678.51 v1(4115.19,6622.29)
  Bottom Layer w5: pad.2@3913,5840 3966.6,5893.6 3966.6,5961.6 3975.5,5970.5 3975.5,6218.8 4115.19,6358.49 v1(4115.19,6622.29)
$Net54: pad.1@4090.5,6532 pad.12@3054.5,7740 pad.74 | length 2665.2
  Top Layer w5: pad.12@3054.5,7740 3095,7780.5 3586,7780.5 3637.5,7729 3637.5,7610.8 3684.4,7563.9 4058.6,7563.9 v1(4090.5,7532) ; pad.74@3698.97,7250.91 3721,7272.94 3721,7301.2 3729.5,7309.7 4071.7,7309.7 v1(4090.5,7290.9) ; pad.1@4090.5,6532 v1(4090.5,6581.5)
  Bottom Layer w5: v1(4090.5,6581.5) v1(4090.5,7290.9) v1(4090.5,7532)
$Net55: pad.9@4313,5940 pad.21@3243.08,6962.05 | length 2178
  Top Layer w5: pad.21@3243.08,6962.05 3268.89,6987.86 v1(3662.36,6987.86) ; v1(3662.36,6019.64) 4233.36,6019.64 pad.9@4313,5940
  Bottom Layer w5: v1(3662.36,6019.64) 3699.6,6056.88 3699.6,6222.2 3778.5,6301.1 3778.5,6613.14 3701.18,6690.46 3701.18,6949.04 v1(3662.36,6987.86)
$Net56: pad.13@2954.5,7640 pad.23@3270.91,6934.21 | length 1665.2
  Top Layer w5: v1(3086,6887.5) 3191.55,6887.5 3212.45,6908.4 3245.1,6908.4 pad.23@3270.91,6934.21
  Bottom Layer w5: pad.13@2954.5,7640 2954.5,7500.5 3042,7413 3217,7413 3300.5,7329.5 3348,7329.5 3418.5,7259 3418.5,7180 3397,7158.5 3379,7158.5 3308.5,7229 3234,7229 3191,7186 3100.5,7186 3086,7171.5 v1(3086,6887.5)
$Net57: pad.11@4413,5940 pad.22@3257,6948.12 | length 2232
  Top Layer w5: pad.22@3257,6948.12 3285.68,6976.8 3624.3,6976.8 v1(3642,6959.1) ; v1(3636,6069) 4284,6069 pad.11@4413,5940
  Bottom Layer w5: v1(3636,6069) 3689.6,6122.6 3689.6,6226.5 3768.5,6305.4 3768.5,6608.99 3691.18,6686.31 3691.18,6909.92 v1(3642,6959.1)
$Net60: pad.17@2754.5,7640 pad.79 | length 1218.1
  Top Layer w5: pad.17@2754.5,7640 2810.9,7696.4 3378.6,7696.4 3409.6,7665.4 3409.6,7617.4 3446,7581 v1(3469.5,7581) ; pad.79@3629.38,7320.5 3664.38,7355.5 v1(3683.5,7355.5)
  Bottom Layer w5: v1(3469.5,7581) 3481.88,7568.62 3481.88,7555.62 3569.6,7467.9 3569.6,7433.5 3647.6,7355.5 v1(3683.5,7355.5)
$Net61: pad.6@3354.5,7740 pad.73 | length 734.7
  Top Layer w5: pad.73@3712.89,7236.99 3738.8,7262.9 v1(3738.8,7290.6)
  Bottom Layer w5: pad.6@3354.5,7740 3414,7680.5 3414,7623.22 3437.72,7599.5 3476,7599.5 3503.5,7572 3541.6,7572 3558.2,7555.4 3558.2,7510.7 3592.3,7476.6 3592.3,7442.5 3635.1,7399.7 3664.1,7399.7 3738.8,7325 v1(3738.8,7290.6)
$Net62: pad.10@3154.5,7740 pad.76 | length 859.9
  Top Layer w5: v1(3615.5,7236.5) 3627.88,7248.88 3641.38,7248.88 3645.32,7252.82 3645.32,7252.94 pad.76@3671.13,7278.75
  Bottom Layer w5: pad.10@3154.5,7740 3204,7690.5 3204,7619.07 3249.07,7574 3406.62,7574 3526.9,7453.72 3526.9,7418 3615.5,7329.4 v1(3615.5,7236.5)
$Net63: pad.8@3254.5,7740 pad.75 | length 847
  Top Layer w5: v1(3652,7231) 3659.24,7238.24 3659.24,7239.01 pad.75@3685.05,7264.82
  Bottom Layer w5: pad.8@3254.5,7740 3214,7699.5 3214,7623.22 3253.22,7584 3410.77,7584 3537,7457.77 3537,7422.5 3652,7307.5 v1(3652,7231)
$Net64: pad.4@3454.5,7740 pad.78 | length 869
  Top Layer w5: pad.78@3643.29,7306.59 3674,7337.3 3700.4,7337.3 3711.1,7348 v1(3819.9,7348)
  Bottom Layer w5: pad.4@3454.5,7740 3495,7699.5 3495,7614.5 3517,7592.5 3627.4,7592.5 3697.7,7522.2 3785.9,7522.2 3838.7,7469.4 3838.7,7366.8 v1(3819.9,7348)
$Net65: pad.2@3554.5,7740 pad.33 | length 1446.9
  Top Layer w5: pad.33@3410.11,6795.01 3478.8,6863.7 3690.4,6863.7 v1(3753.5,6926.8)
  Bottom Layer w5: pad.2@3554.5,7740 3595,7740 3635,7700 3635,7636.7 3710,7561.7 3775.4,7561.7 3860.5,7476.6 3860.5,7348.5 3813.4,7301.4 3813.4,7259.1 3816.5,7256 3816.5,6989.8 v1(3753.5,6926.8)
$Net66: pad.16@3712.5,7742 pad.66 | length 702
  Top Layer w5: pad.66@3810.32,7139.55 3849.26,7178.49 v1(3849.26,7219.35)
  Bottom Layer w5: pad.16@3712.5,7742 3762.1,7692.4 3762.1,7608.8 3881.6,7489.3 3881.6,7318.4 3849.26,7286.06 v1(3849.26,7219.35)
$Net67: pad.14@3812.5,7742 pad.65 | length 686
  Top Layer w5: pad.65@3824.25,7125.63 3868.88,7170.26 v1(3868.88,7190.36)
  Bottom Layer w5: pad.14@3812.5,7742 3860.5,7694 3860.5,7621.5 3902.4,7579.6 3902.4,7223.88 v1(3868.88,7190.36)
$Net68: pad.1@4412.5,7642 pad.64 | length 1060.7
  Top Layer w5: pad.64@3838.16,7111.71 3863.97,7137.52 3863.97,7150.3 3879.67,7166 v1(4379,7166)
  Bottom Layer w5: v1(4379,7166) 4412.5,7199.5 pad.1@4412.5,7642
$Net69: pad.10@4012.5,7742 pad.30@3368.35,6836.77 | length 1492.5
  Top Layer w5: pad.30@3368.35,6836.77 3429.38,6897.8 3662.3,6897.8 3780.5,7016 3924.5,7016 v1(3949.5,6991)
  Bottom Layer w5: v1(3949.5,6991) 3949.5,7014.6 3936,7028.1 3936,7112.25 3943.3,7119.55 3943.3,7489.8 4059,7605.5 4059,7695.5 pad.10@4012.5,7742
$Net70: pad.6@4212.5,7742 pad.77 | length 936.2
  Top Layer w5: pad.77@3657.21,7292.66 3689.65,7325.1 3702.6,7325.1 3708,7330.5 v1(4133.5,7330.5)
  Bottom Layer w5: v1(4133.5,7330.5) 4162.5,7359.5 4162.5,7692 pad.6@4212.5,7742
$Net71: pad.1@3304.5,6803 pad.4@4312.5,7742 pad.28@3340.51,6864.61 | length 1831.9
  Top Layer w5: pad.1@3304.5,6803 3304.5,6828.6 pad.28@3340.51,6864.61 3383.9,6908 3658.35,6908 3776.35,7026 3942.15,7026 3962.65,7005.5 v1(4264,7005.5)
  Bottom Layer w5: v1(4264,7005.5) 4264,7693.5 pad.4@4312.5,7742
$Net72: pad.1@3246.5,6803 pad.2@4412.5,7742 pad.27@3326.59,6878.53 | length 1955
  Top Layer w5: pad.1@3246.5,6803 3246.5,6828 3255.5,6837 3285.06,6837 pad.27@3326.59,6878.53 3367.56,6919.5 3655.7,6919.5 3772.2,7036 4326.5,7036 4332.5,7030 v1(4350,7030)
  Bottom Layer w5: v1(4350,7030) 4350,7604 4359,7613 4359,7688.5 pad.2@4412.5,7742
$Net73: pad.19@2654.5,7640 pad.80 | length 1323.4
  Top Layer w5: pad.19@2654.5,7640 2695,7640 2738,7597 2782,7597 2804.7,7619.7 2804.7,7654.2 2836.7,7686.2 3373.6,7686.2 3399.3,7660.5 3399.3,7613.54 3458.35,7554.5 v1(3523,7554.5) ; pad.80@3615.45,7334.42 3642.82,7361.79 3642.82,7364.22 v1(3655.2,7376.6)
  Bottom Layer w5: v1(3523,7554.5) 3523,7531.5 3579.9,7474.6 3579.9,7440.6 3631.52,7388.98 3642.82,7388.98 v1(3655.2,7376.6)
$Net74: pad.3@4312.5,7642 pad.55 | length 1346.3
  Top Layer w5: pad.55@3810.32,6892.45 3836.13,6866.64 3844.86,6866.64 3897.5,6814 4284.5,6814 v1(4310,6839.5)
  Bottom Layer w5: v1(4310,6839.5) 4310,7593 4312.5,7595.5 pad.3@4312.5,7642
$Net75: pad.12@3912.5,7742 pad.31@3382.27,6822.85 | length 1416.2
  Top Layer w5: pad.31@3382.27,6822.85 3446.72,6887.3 3669.65,6887.3 3788.35,7006 3897.5,7006 v1(3914.5,6989)
  Bottom Layer w5: pad.12@3912.5,7742 3959,7695.5 3959,7622.73 3922.5,7586.23 3922.5,7159.33 3902,7138.83 3902,7122.75 3902.12,7122.63 3902.12,7001.38 v1(3914.5,6989)
$Net76: pad.8@4112.5,7742 pad.32@3396.19,6808.93 | length 1631.5
  Top Layer w5: pad.32@3396.19,6808.93 3463.46,6876.2 3672.7,6876.2 3792.5,6996 3876,6996 3901,6971 4105,6971 4109.5,6975.5 v1(4127,6975.5) ; pad.8@4112.5,7742 4159,7695.5 4159,7566.5 v1(4127,7534.5)
  Bottom Layer w5: v1(4127,6975.5) 4112.5,6990 4112.5,7343.6 4127,7358.1 v1(4127,7534.5)
$Net77: pad.52 | length 974.4
  Top Layer w5: pad.52@3768.57,6850.69 3827.76,6791.5 v1(4414.5,6791.5)
  Bottom Layer w5: v1(4414.5,6791.5) v1(4718.5,6791.5)
$Net78: pad.1@2674.1,6477.9 pad.12@4413,5840 pad.56 | length 3518.5
  Top Layer w5: v1(2668.9,6782.6) 2686.4,6782.6 2827.2,6641.8 2845.4,6641.8 2887.8,6599.4 3119.5,6599.4 v1(3180.3,6538.6) ; pad.1@2674.1,6477.9 2674.1,6505.5 2683,6514.4 v1(2683,6514.3) ; v1(3249.9,6608.1) 3280.6,6608.1 3372.52,6700.02 3372.52,6707.22 v1(3384.9,6719.6) ; v1(3461,6814.7) 3489.7,6843.4 3701.5,6843.4 3790.28,6932.18 3798.44,6932.18 pad.56@3824.25,6906.37 3906.62,6824 4265,6824 4306.5,6865.5 v1(4391.5,6865.5)
  Bottom Layer w5: v1(2668.9,6782.6) 2689.6,6761.9 2689.6,6719.6 2632.5,6662.5 2632.5,6588.9 2683,6538.4 v1(2683,6514.3) ; v1(3180.3,6538.6) 3192.68,6550.98 3192.78,6550.98 v1(3249.9,6608.1) ; v1(3384.9,6719.6) 3384.9,6761 3438.6,6814.7 v1(3461,6814.7) ; v1(4391.5,6865.5) 4391.5,6041.24 4467.6,5965.14 4467.6,5894.6 pad.12@4413,5840
$Net80: pad.10@4313,5840 pad.57 | length 1732.2
  Top Layer w5: pad.57@3838.16,6920.29 3923.95,6834.5 4258.5,6834.5 4332.5,6908.5 v1(4370.5,6908.5)
  Bottom Layer w5: pad.10@4313,5840 4362.9,5889.9 4362.9,5967.7 4313,6017.6 4313,6775 4370.5,6832.5 v1(4370.5,6908.5)
$Net81: pad.1@2863.5,6452.13 pad.1@2863.5,6504 pad.2@2582.29,6625.5 pad.27@2703.22,6314.93 | length 798.6
  Top Layer w5: pad.2@2582.29,6625.5 2582.29,6682.49 2598.3,6698.5 2723.6,6698.5 2863.5,6558.6 v1(2863.5,6536.4) pad.1@2863.5,6452.13 2863.5,6384.13 2857.77,6378.4 2813.9,6378.4 2765.63,6330.13 2718.42,6330.13 pad.27@2703.22,6314.93
  Bottom Layer w5: pad.1@2863.5,6504 v1(2863.5,6536.4)
$Net82: 
$Net83: pad.1@2725.99,6432 pad.1@2728.5,6431 pad.29@2675.36,6342.79 | length 188.4
  Top Layer w5: pad.29@2675.36,6342.79 2691.57,6359 2727,6359 2738.5,6370.5 v1(2738.5,6388) 2725.99,6400.51 pad.1@2725.99,6432
  Bottom Layer w5: pad.1@2728.5,6431 2728.5,6398 v1(2738.5,6388)
$Net84: pad.1@2556.7,6625.5 pad.1@2842,6246.5 pad.20@2675.36,6195.21 | length 1057.1
  Top Layer w5: pad.1@2556.7,6625.5 2556.7,6685.7 2582,6711 2726,6711 2815.72,6621.28 2826.32,6621.28 v2(2838.7,6608.9) ; pad.20@2675.36,6195.21 2690.56,6180.01 2798.11,6180.01 2805.6,6187.5 v1(2805.6,6221.6) 2805.6,6231.6 2820.5,6246.5 pad.1@2842,6246.5
  Bottom Layer w5: v1(2805.6,6221.6) 2793.22,6233.98 2793.22,6244.3 2779.5,6258.02 2779.5,6326 2785.5,6332 2785.5,6578.2 2816.2,6608.9 v2(2838.7,6608.9)
$Net85: pad.2@2944,7081 pad.3@2607.88,6625.5 pad.9@2684.65,6901.1 pad.29@3354.43,6850.69 | length 1401.2
  Top Layer w5: pad.3@2607.88,6625.5 2608,6625.62 v1(2608,6677.5) ; v1(2684.65,6841.85) pad.9@2684.65,6901.1 2684.65,7028.25 2765.9,7109.5 2915.5,7109.5 pad.2@2944,7081 2996.5,7081 3047.5,7030 v1(3386,7030) ; pad.29@3354.43,6850.69 3380.66,6876.92 3381.02,6876.92 v1(3393.4,6889.3)
  Bottom Layer w5: v1(2608,6677.5) 2623.1,6692.6 2623.1,6780.3 v1(2684.65,6841.85) ; v1(3386,7030) 3386,6979.9 3393.4,6972.5 v1(3393.4,6889.3)
$Net86: pad.1@2131.5,7578 pad.1@2162.5,7576 pad.1@2213.2,7630.1 pad.1@2279,6696.4 pad.1@2279,7527.5 | length 1469.9
  Top Layer w25: pad.1@2213.2,7630.1 2212.8,7630.5 v2(2162.5,7630.5) pad.1@2162.5,7576 2162.5,7536 2171,7527.5 pad.1@2279,7527.5
  Bottom Layer w25: v2(2162.5,7630.5) 2131.5,7599.5 pad.1@2131.5,7578 2131.5,7507.9 1985.5,7361.9 1985.5,6861 2150.1,6696.4 pad.1@2279,6696.4
$Net87: pad.1@3827.5,6540 pad.1@3898.44,6478.53 pad.1@3931.5,6540 | length 171.7
  Top Layer w5: pad.1@3827.5,6540 v1(3883.5,6540) 3898.44,6525.06 pad.1@3898.44,6478.53
  Bottom Layer w5: v1(3883.5,6540) pad.1@3931.5,6540
$Net88: pad.1@3978.5,6540 pad.1@4016.5,6611 pad.4@4016.56,6478.53 | length 180
  Top Layer w5: pad.1@4016.5,6611 v1(4016.5,6563) 4016.5,6478.59 pad.4@4016.56,6478.53
  Bottom Layer w5: pad.1@3978.5,6540 4001.5,6563 v1(4016.5,6563)
$Net89: pad.1@4090.5,6471 pad.1@4090.5,6472 pad.3@4016.56,6419.47 | length 173.3
  Top Layer w5: pad.3@4016.56,6419.47 4066.47,6419.47 4069,6422 v1(4086.5,6422) 4086.5,6439.5 4090.5,6443.5 pad.1@4090.5,6472
  Bottom Layer w5: v1(4086.5,6422) 4086.5,6439.5 4090.5,6443.5 pad.1@4090.5,6471
$Net90: pad.1@2018.5,6897.3 pad.1@2145.5,6897 pad.1@2205.5,6897 pad.6@3210.04,5840.58 pad.10@2944,6881 pad.21@2689.29,6209.14 pad.42 | length 3765.5
  Top Layer w5: pad.1@2018.5,6897.3 2057.5,6897.3 2057.8,6897 pad.1@2145.5,6897 pad.1@2205.5,6897 2249.5,6897 2296.5,6850 2380.5,6850 2499.5,6969 2499.5,6989 2564,7053.5 v1(2670.5,7053.5) ; pad.21@2689.29,6209.14 2699.92,6198.5 v1(2779.2,6198.5) ; v1(2752.1,7047.4) 2771.1,7047.4 2793.5,7025 2793.5,6896.5 2844.5,6845.5 2908.5,6845.5 pad.10@2944,6881 2998.5,6881 3029,6911.5 3164,6911.5 3251.6,6999.1 3574.3,6999.1 v1(3588,7012.8) ; v1(3588,6758.5) 3600.38,6746.12 3600.38,6740.5 pad.42@3629.38,6711.5
  Bottom Layer w5: v1(2670.5,7053.5) 2728.5,7053.5 2734.6,7047.4 v1(2752.1,7047.4) ; pad.10@2944,6881 2956,6869 2956,6798.6 2774.5,6617.1 2774.5,6337 2768.5,6331 2768.5,6251.8 2779.2,6241.1 v1(2779.2,6198.5) 2799.5,6198.5 2820.9,6177.1 2820.9,6066.9 2930.9,5956.9 2930.9,5916.4 2957.3,5890 3160.58,5890 3177.14,5873.46 pad.6@3210.04,5840.58 ; v1(3588,6758.5) v1(3588,7012.8)
$Net91: 
$Net92: pad.1@2710.5,6120 pad.1@2833,6063.5 pad.1@2833,6120.5 pad.10@2323.5,6000 pad.19@2661.43,6181.28 | length 842.3
  Top Layer w5: pad.19@2661.43,6181.28 2676.63,6166.08 2700.12,6166.08 2747.2,6119 v1(2767,6119) 2784.5,6119 2786,6120.5 pad.1@2833,6120.5 pad.1@2833,6063.5
  Bottom Layer w5: pad.10@2323.5,6001 2335.5,6013 2352,6013 2354,6011 2483,6011 2588.8,6116.8 2588.8,6144.8 2627.1,6183.1 2687.9,6183.1 2710.5,6160.5 pad.1@2710.5,6120 2711.5,6119 v1(2767,6119)
$Net96: pad.1@2302.5,6301.5 pad.1@2457.5,6408 pad.3@2195.2,6378.2 | length 385
  Top Layer w20: pad.3@2195.2,6378.2 2195.5,6378.5 2259,6378.5 v2(2264.5,6373)
  Top Layer w22: pad.1@2302.5,6301.5 2303,6301.5 2325.5,6324 2325.5,6341.48 v1(2317.98,6349) 2317.98,6362.48 2359.5,6404 2421,6404 2425,6408 pad.1@2457.5,6408
  Bottom Layer w22: v2(2264.5,6373) 2271.26,6379.76 2306.14,6379.76 2319.1,6366.8 2319.1,6350.12 v1(2317.98,6349)
$Net97: pad.1@2376.5,6301.5 pad.1@2457.5,6370 pad.2@2195.2,6409.7 | length 383.6
  Top Layer w20: pad.2@2195.2,6409.7 2259.68,6409.7 v1(2264.5,6414.52)
  Top Layer w22: pad.1@2376.5,6301.5 2376.5,6302 2353.5,6325 2353.5,6343 v2(2359.5,6349) 2359.5,6364.4 2371.1,6376 2419,6376 2425,6370 pad.1@2457.5,6370
  Bottom Layer w22: v1(2264.5,6414.52) 2271.26,6407.76 2317.74,6407.76 2359.5,6366 v2(2359.5,6349)
$Net109: pad.1@2132.4,6105.2 pad.2@2123.5,6000 pad.15@2583.5,6167.35 | length 586.4
  Top Layer w5: pad.2@2123.5,6001 2123.5,6060.4 2132.5,6069.4 2132.5,6073.21 pad.1@2132.4,6105.2 2184.7,6105.2 v1(2204.5,6125) ; v1(2559.88,6143) 2559.88,6143.73 pad.15@2583.5,6167.35
  Bottom Layer w5: v1(2204.5,6125) 2222,6125 2222.5,6124.5 2319.5,6124.5 2339,6144 2521,6144 2522,6143 v1(2559.88,6143)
